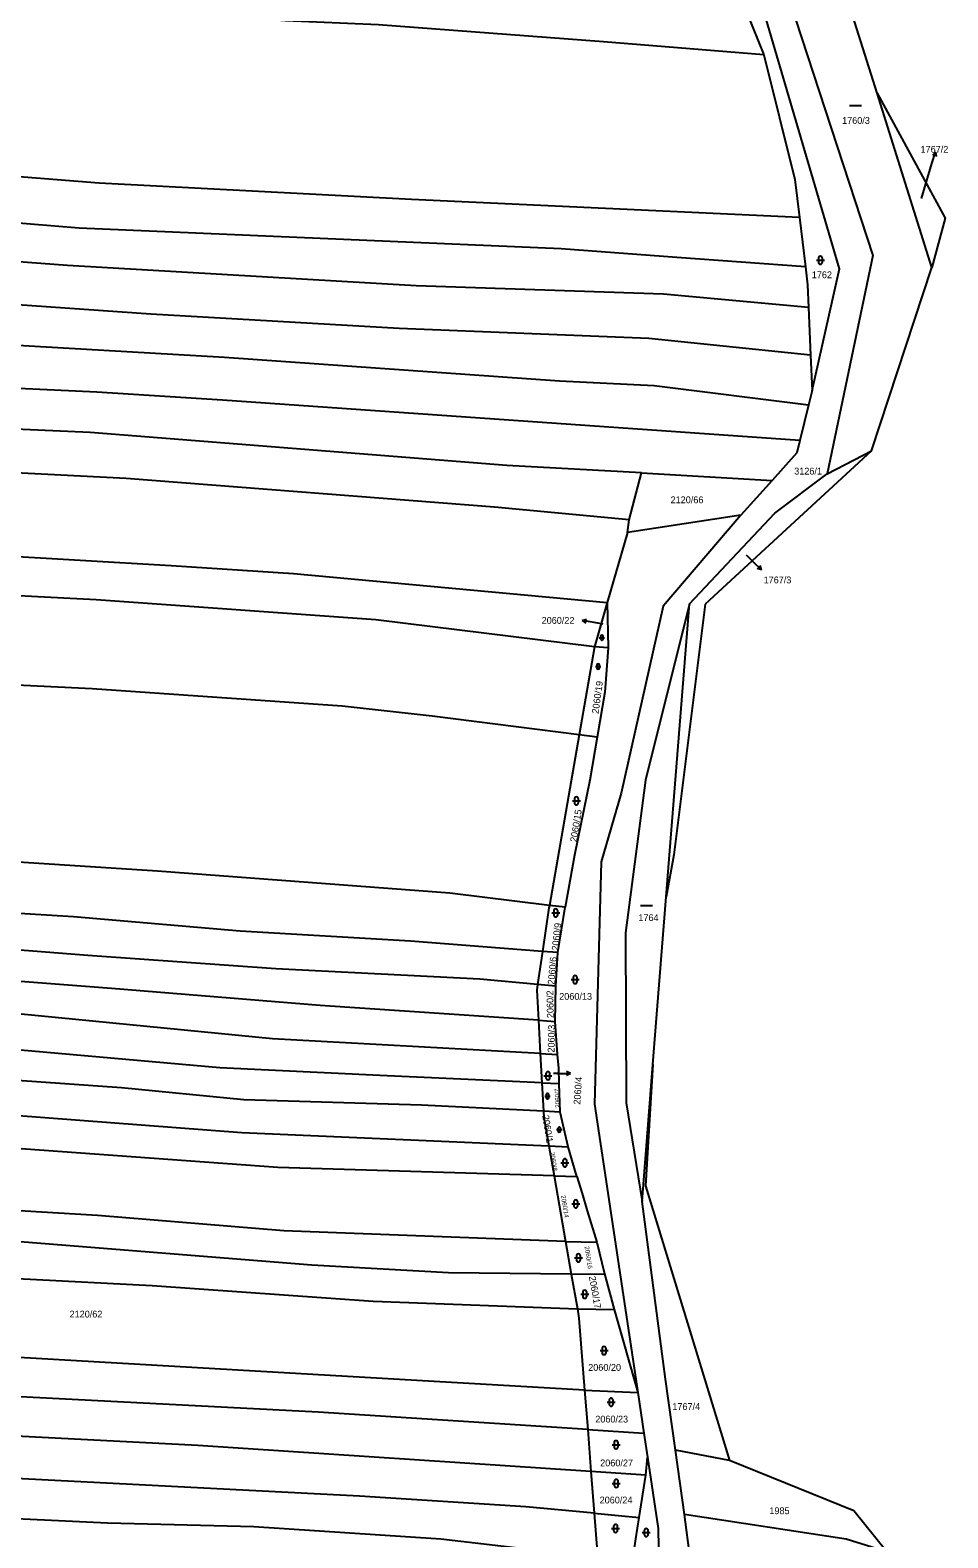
# Model space of a CAD drawing. Extents: x -755528 to -748832, y -1118122 to -1111095.
# Drawn here: x -753247.8 to -753018, y -1116748.3 to -1116370.9 of the extents above; entities that cross this region are included whole.
import ezdxf

# ---------------------------------------------------------------- set-up
doc = ezdxf.new("R2010")
doc.units = 0
for name, color, linetype in [('DZ_DO_PUPFL', 7, 'Continuous'), ('DZ_NAD_ZPF', 7, 'Continuous'), ('legenda barvy', 7, 'Continuous'), ('TZ_UMVŽST', 7, 'Continuous')]:
    doc.layers.add(name, color=color, linetype=linetype)

msp = doc.modelspace()

# ---------------------------------------------------------------- linework, layer by layer
at = {"layer": 'DZ_NAD_ZPF'}
for p, q in [((-753035.72, -1116386.71), (-753043.48, -1116361.95)), ((-753068.32, -1116366.58), (-753064.04, -1116377.12)), ((-753022.04, -1116430.33), (-753035.72, -1116386.71)), ((-753055.15, -1116417.85), (-753053.67, -1116430.18)), ((-753037.1, -1116476.19), (-753022.04, -1116430.33)), ((-753052.89, -1116440.36), (-753052.37, -1116452.3)), ((-753052.37, -1116452.3), (-753051.98, -1116461.16)), ((-753051.98, -1116461.16), (-753052.87, -1116464.8)), ((-753052.87, -1116464.8), (-753055.04, -1116473.63)), ((-753037.1, -1116476.19), (-753078.79, -1116514.61)), ((-753048.23, -1116481.98), (-753037.1, -1116476.19)), ((-753097.82, -1116493.49), (-753094.72, -1116481.73)), ((-753094.72, -1116481.73), (-753062.02, -1116483.62)), ((-753062.02, -1116483.62), (-753069.85, -1116492.32)), ((-753069.85, -1116492.32), (-753098.18, -1116496.71)), ((-753098.18, -1116496.71), (-753097.82, -1116493.49)), ((-753098.18, -1116496.71), (-753103.26, -1116514.2)), ((-753103.26, -1116514.2), (-753106.48, -1116525.3)), ((-753103.26, -1116514.2), (-753103.08, -1116525.57)), ((-753088.48, -1116587.88), (-753082.66, -1116514.55)), ((-753078.79, -1116514.61), (-753086.62, -1116577.36)), ((-753106.48, -1116525.3), (-753110.32, -1116547.29)), ((-753103.08, -1116525.57), (-753106.48, -1116525.3)), ((-753110.32, -1116547.29), (-753117.77, -1116590.01)), ((-753105.78, -1116547.92), (-753110.32, -1116547.29)), ((-753086.62, -1116577.36), (-753088.48, -1116587.88)), ((-753091.82, -1116629.84), (-753088.48, -1116587.88)), ((-753113.79, -1116590.48), (-753117.77, -1116590.01)), ((-753115.61, -1116601.82), (-753113.79, -1116590.48)), ((-753119.5, -1116601.51), (-753120.73, -1116609.8)), ((-753115.61, -1116601.82), (-753119.5, -1116601.51)), ((-753116.16, -1116610.22), (-753115.61, -1116601.82)), ((-753116.16, -1116610.22), (-753120.73, -1116609.8)), ((-753116.32, -1116619.03), (-753116.16, -1116610.22)), ((-753120.51, -1116618.75), (-753116.32, -1116619.03)), ((-753120.51, -1116618.75), (-753120.03, -1116627.07)), ((-753115.75, -1116627.3), (-753116.32, -1116619.03)), ((-753120.03, -1116627.07), (-753115.75, -1116627.3)), ((-753120.03, -1116627.07), (-753119.61, -1116634.4)), ((-753094.54, -1116664.14), (-753091.82, -1116629.84)), ((-753119.61, -1116634.4), (-753119.2, -1116641.49)), ((-753119.61, -1116634.4), (-753115.3, -1116634.59)), ((-753115.03, -1116641.73), (-753115.3, -1116634.59)), ((-753115.03, -1116641.73), (-753119.2, -1116641.49)), ((-753113.04, -1116650.4), (-753115.03, -1116641.73)), ((-753117.87, -1116650.19), (-753116.57, -1116657.66)), ((-753117.87, -1116650.19), (-753113.04, -1116650.4)), ((-753110.88, -1116657.83), (-753113.04, -1116650.4)), ((-753116.57, -1116657.66), (-753110.88, -1116657.83)), ((-753116.57, -1116657.66), (-753113.7, -1116674.1)), ((-753113.7, -1116674.1), (-753105.9, -1116674.32)), ((-753113.7, -1116674.1), (-753112.28, -1116682.26)), ((-753105.9, -1116674.32), (-753103.94, -1116682.22)), ((-753112.28, -1116682.26), (-753103.94, -1116682.22)), ((-753112.28, -1116682.26), (-753110.76, -1116690.99)), ((-753103.94, -1116682.22), (-753101.55, -1116691.1)), ((-753110.76, -1116690.99), (-753101.55, -1116691.1)), ((-753101.55, -1116691.1), (-753095.65, -1116711.88)), ((-753108.94, -1116711.3), (-753095.65, -1116711.88)), ((-753108.94, -1116711.3), (-753108.17, -1116721.19)), ((-753095.65, -1116711.88), (-753094.12, -1116722.1)), ((-753108.17, -1116721.19), (-753094.12, -1116722.1)), ((-753108.17, -1116721.19), (-753107.35, -1116731.69)), ((-753094.12, -1116722.1), (-753093.23, -1116728.07)), ((-753093.58, -1116732.6), (-753093.23, -1116728.07)), ((-753083.97, -1116742.45), (-753086.2, -1116726.32)), ((-753072.62, -1116728.96), (-753086.2, -1116726.32)), ((-753093.58, -1116732.6), (-753107.35, -1116731.69)), ((-753107.35, -1116731.69), (-753106.54, -1116742.11)), ((-753095.25, -1116743.18), (-753093.58, -1116732.6)), ((-753106.54, -1116742.11), (-753095.25, -1116743.18)), ((-753082.48, -1116753.28), (-753083.97, -1116742.45))]:
    msp.add_line(p, q, dxfattribs=at)
for points in [[(-753080.93, -1116306.6), (-753057.65, -1116363.64), (-753036.75, -1116427.3), (-753048.23, -1116481.98)], [(-753051.98, -1116461.16), (-753045.09, -1116430.7), (-753063.87, -1116366.8), (-753089.17, -1116309.16)], [(-753064.04, -1116377.12), (-753104.25, -1116373.86), (-753160.52, -1116369.63), (-753183.87, -1116368.63), (-753300.7, -1116360.15), (-753407.6, -1116353.37), (-753482.36, -1116346.9), (-753577.16, -1116338.42), (-753615.37, -1116334.2), (-753662.17, -1116330.3)], [(-753055.15, -1116417.85), (-753152.31, -1116413.29), (-753230.45, -1116409.21), (-753283.15, -1116405.05), (-753353.24, -1116400.32), (-753415.19, -1116395.32), (-753486.23, -1116390.03), (-753599.85, -1116379.59), (-753670.46, -1116375.3)], [(-753064.04, -1116377.12), (-753056.29, -1116408.34), (-753055.15, -1116417.85)], [(-753053.67, -1116430.18), (-753085.86, -1116427.83), (-753114.81, -1116425.67), (-753235.46, -1116420.46), (-753284.32, -1116416.49), (-753372.74, -1116409.15), (-753409.95, -1116406.88), (-753498.22, -1116401.1), (-753576.32, -1116394.9), (-753643.94, -1116389.17), (-753670.38, -1116387.43)], [(-753035.72, -1116386.71), (-753018.67, -1116417.96), (-753022.04, -1116430.33)], [(-753052.89, -1116440.36), (-753089.2, -1116436.99), (-753151.1, -1116434.97), (-753238.4, -1116429.86), (-753343.18, -1116421.97), (-753441.89, -1116414.39), (-753537.49, -1116408.03), (-753670.32, -1116397.5)], [(-753052.37, -1116452.3), (-753092.82, -1116448.08), (-753155.39, -1116445.6), (-753217.57, -1116442.02), (-753293.95, -1116436.66), (-753394.99, -1116429.88), (-753425.51, -1116426.7), (-753513.73, -1116419.12), (-753575.06, -1116415.73), (-753646.53, -1116409.65), (-753670.26, -1116408.28)], [(-753052.87, -1116464.8), (-753091.55, -1116460), (-753115.19, -1116458.82), (-753199.07, -1116452.86), (-753294.13, -1116447.38), (-753346.4, -1116444.01), (-753446.46, -1116435.5), (-753517.38, -1116429.36), (-753571.65, -1116426.23), (-753670.2, -1116418.61)], [(-753055.04, -1116473.63), (-753199.61, -1116463.54), (-753231.11, -1116461.58), (-753291.76, -1116458.74), (-753351.06, -1116454.14), (-753446.92, -1116446.07), (-753544.62, -1116438.64), (-753670.14, -1116429.12)], [(-753053.67, -1116430.18), (-753053.13, -1116434.72), (-753052.89, -1116440.36)], [(-753094.72, -1116481.73), (-753128.44, -1116479.94), (-753232.75, -1116471.64), (-753296.62, -1116468.8), (-753350.3, -1116464.81), (-753423.98, -1116458.3), (-753499.67, -1116452.31), (-753630.09, -1116442.54), (-753669.86, -1116439.26)], [(-753097.82, -1116493.49), (-753131.52, -1116490.29), (-753223.69, -1116483.13), (-753328.35, -1116477.8), (-753409.55, -1116472.01), (-753516.73, -1116463.2)], [(-753055.04, -1116473.63), (-753055.79, -1116476.7), (-753062.02, -1116483.62)], [(-753106.48, -1116525.3), (-753161.19, -1116518.53), (-753231.25, -1116513.52), (-753287.98, -1116510.58), (-753339.87, -1116507.71), (-753451.87, -1116500.04), (-753528.85, -1116494.44), (-753580.02, -1116490.13), (-753668, -1116483.8)], [(-753082.66, -1116514.55), (-753061.33, -1116491.86), (-753048.23, -1116481.98)], [(-753516.65, -1116484.51), (-753408.18, -1116492.28), (-753303.67, -1116499.59), (-753212.42, -1116504.93), (-753181.8, -1116506.9), (-753103.26, -1116514.2)], [(-753069.85, -1116492.32), (-753089.31, -1116515.12), (-753099.78, -1116561.94), (-753104.82, -1116579.08), (-753106.45, -1116639.73), (-753095.65, -1116711.88)], [(-753110.32, -1116547.29), (-753147.07, -1116542.64), (-753169.63, -1116540.12), (-753232.26, -1116535.78), (-753292.49, -1116532.85), (-753379.65, -1116525.65), (-753447.94, -1116522.54), (-753498.54, -1116518.16), (-753546.82, -1116513.62), (-753672.92, -1116505)], [(-753082.66, -1116514.55), (-753093.68, -1116558.63), (-753098.7, -1116596.86), (-753098.57, -1116639.41), (-753094.54, -1116664.14)], [(-753103.08, -1116525.57), (-753103.84, -1116536.62), (-753105.78, -1116547.92)], [(-753105.78, -1116547.92), (-753107.63, -1116558.62), (-753111.5, -1116577.43), (-753113.79, -1116590.48)], [(-753117.77, -1116590.01), (-753142.67, -1116586.97), (-753215.84, -1116581.41), (-753338.69, -1116573.51), (-753453.85, -1116566.25), (-753560.24, -1116557.34), (-753628.34, -1116552.85), (-753684.94, -1116548.9)], [(-753119.5, -1116601.51), (-753152.5, -1116598.92), (-753195.18, -1116596.48), (-753236.95, -1116592.88), (-753280.41, -1116590.2), (-753356.07, -1116586.47), (-753458.55, -1116577.59), (-753551.39, -1116570), (-753603.3, -1116567.29), (-753639.97, -1116564.72), (-753686.88, -1116561.68)], [(-753120.73, -1116609.8), (-753135.15, -1116608.49), (-753186.22, -1116605.85), (-753233.31, -1116602.56), (-753283.22, -1116598.63), (-753342.44, -1116595.55), (-753426.53, -1116589.69), (-753512.16, -1116581.9), (-753589.34, -1116577.17), (-753645.57, -1116573), (-753687.95, -1116569.77)], [(-753120.51, -1116618.75), (-753175.16, -1116615.05), (-753227.4, -1116610.81), (-753283.87, -1116606.45), (-753334.32, -1116604.33), (-753371.87, -1116602.55), (-753439.51, -1116597.13), (-753519.95, -1116590.26), (-753583.2, -1116585.55), (-753688.11, -1116577.63)], [(-753120.03, -1116627.07), (-753187.11, -1116623.41), (-753250.02, -1116617.19), (-753303.43, -1116613.35), (-753360.24, -1116611.05), (-753425.93, -1116606.46), (-753537.39, -1116597.42), (-753589.17, -1116592.82), (-753629.29, -1116589.75), (-753689.1, -1116586.33)], [(-753117.77, -1116590.01), (-753117.88, -1116590.65), (-753119.5, -1116601.51)], [(-753119.61, -1116634.4), (-753160.2, -1116632.57), (-753200.27, -1116630.64), (-753264.38, -1116624.95), (-753343.29, -1116620.22), (-753416.78, -1116616.19), (-753496.78, -1116610.31), (-753555.04, -1116605.14), (-753612.79, -1116599.7), (-753690.93, -1116594.68)], [(-753119.2, -1116641.49), (-753149.74, -1116639.98), (-753194.27, -1116638.67), (-753224.91, -1116635.7), (-753265.19, -1116632.8), (-753381.97, -1116625.61), (-753432.26, -1116621.91), (-753505.62, -1116617.63), (-753520.93, -1116615.25), (-753583.34, -1116609.73), (-753660.46, -1116604.37), (-753691.22, -1116602.59)], [(-753691.52, -1116610.78), (-753600.79, -1116616.91), (-753502.59, -1116625.81), (-753417.49, -1116632.43), (-753347.21, -1116636.8), (-753277.07, -1116640.61), (-753194.79, -1116646.87), (-753117.87, -1116650.19)], [(-753120.73, -1116609.8), (-753120.94, -1116611.18), (-753120.51, -1116618.75)], [(-753116.57, -1116657.66), (-753185.72, -1116655.57), (-753262.72, -1116650), (-753343.14, -1116644.53), (-753421.14, -1116639.55), (-753499.3, -1116633.88), (-753572.2, -1116628.31), (-753650.2, -1116621.85), (-753692.11, -1116619)], [(-753115.3, -1116634.59), (-753115.39, -1116630.7), (-753115.75, -1116627.3)], [(-753091.82, -1116629.84), (-753093.69, -1116660.21), (-753072.62, -1116728.96)], [(-753113.7, -1116674.1), (-753184.28, -1116671.43), (-753230.92, -1116667.63), (-753302.09, -1116663.36), (-753346.03, -1116660.91), (-753369.09, -1116659.88), (-753452.17, -1116652.28), (-753531.92, -1116647.85), (-753588.93, -1116643.89), (-753693.33, -1116634.36)], [(-753112.28, -1116682.26), (-753143.04, -1116681.96), (-753177.27, -1116680.01), (-753249.3, -1116674.3), (-753338.53, -1116670.13), (-753365.38, -1116668.86), (-753404.76, -1116665.41), (-753438.55, -1116662.23), (-753528.82, -1116656.42), (-753589.87, -1116652.44), (-753648.02, -1116647.27), (-753693.98, -1116642.62)], [(-753119.2, -1116641.49), (-753119.11, -1116643.08), (-753117.87, -1116650.19)], [(-753110.88, -1116657.83), (-753109.59, -1116662.14), (-753108.27, -1116666.43), (-753105.9, -1116674.32)], [(-753086.2, -1116726.32), (-753088.65, -1116708.56), (-753094.54, -1116664.14)], [(-753409.87, -1116673.16), (-753374.3, -1116676.81), (-753341.36, -1116678.85), (-753286.53, -1116681.56), (-753217.25, -1116685.12), (-753161.87, -1116689.03), (-753110.76, -1116690.99)], [(-753108.17, -1116721.19), (-753175.69, -1116716.83), (-753266.56, -1116712.19), (-753376.27, -1116705.64), (-753420.79, -1116703.46), (-753487.86, -1116699.64), (-753570.08, -1116693.1), (-753642.51, -1116686.62), (-753699.29, -1116681.76)], [(-753107.35, -1116731.69), (-753205.79, -1116725.18), (-753301.79, -1116720.22), (-753356.45, -1116717.9), (-753461.67, -1116711.76), (-753564.03, -1116704.34), (-753655.25, -1116696.46), (-753702.04, -1116690.26)], [(-753110.76, -1116690.99), (-753110.35, -1116693.33), (-753108.94, -1116711.3)], [(-753108.94, -1116711.3), (-753177.01, -1116707.37), (-753364.68, -1116696.59), (-753411.06, -1116693.38)], [(-753106.54, -1116742.11), (-753123.64, -1116740.5), (-753165.33, -1116737.82), (-753309.88, -1116730.42), (-753409.98, -1116725.28), (-753491.42, -1116720.46), (-753545.86, -1116715.21), (-753574.03, -1116711.78), (-753642.9, -1116705.03), (-753704.07, -1116695.71)], [(-753691.95, -1116706.77), (-753643.72, -1116716.2), (-753541.02, -1116725.82), (-753441.66, -1116735.38), (-753390.15, -1116736.89), (-753228.4, -1116744.56), (-753191.78, -1116745.46), (-753144.93, -1116748.5), (-753118.45, -1116751.61), (-753105.5, -1116753.63)], [(-753093.23, -1116728.07), (-753090.55, -1116745.92), (-753090.36, -1116755.4), (-753100.53, -1116786.86)], [(-753033.24, -1116751.75), (-753041.57, -1116741.52), (-753072.62, -1116728.96)], [(-753106.54, -1116742.11), (-753105.79, -1116751.69), (-753105.5, -1116753.63)], [(-753097.06, -1116754.82), (-753096.15, -1116748.55), (-753095.25, -1116743.18)], [(-753033.24, -1116751.75), (-753043.44, -1116748.63), (-753083.97, -1116742.45)]]:
    msp.add_lwpolyline(points, dxfattribs=at)
at = {"layer": 'legenda barvy'}
for p, q in [((-753024.59, -1116413.11), (-753021.96, -1116404.35)), ((-753021.96, -1116404.35), (-753021.083, -1116401.48)), ((-753021.083, -1116401.48), (-753021.854, -1116402.291)), ((-753021.083, -1116401.48), (-753020.897, -1116402.584)), ((-753068.48, -1116502.3), (-753066.81, -1116503.92)), ((-753066.81, -1116503.92), (-753064.651, -1116506.005)), ((-753064.651, -1116506.005), (-753065.72, -1116505.669)), ((-753064.651, -1116506.005), (-753065.024, -1116504.949)), ((-753109.515, -1116518.669), (-753108.442, -1116518.35)), ((-753106.56, -1116519.19), (-753109.515, -1116518.669)), ((-753109.515, -1116518.669), (-753108.616, -1116519.336)), ((-753104.29, -1116519.59), (-753106.56, -1116519.19)), ((-753115.5, -1116632.1), (-753116.71, -1116632.1)), ((-753115.5, -1116632.1), (-753112.499, -1116632.1)), ((-753112.499, -1116632.1), (-753113.5, -1116631.599)), ((-753112.499, -1116632.1), (-753113.5, -1116632.601))]:
    msp.add_line(p, q, dxfattribs=at)
at = {"layer": 'TZ_UMVŽST'}
for p, q in [((-753042.628, -1116389.83), (-753039.628, -1116389.83)), ((-753050.911, -1116428.511), (-753048.909, -1116428.511)), ((-753050.411, -1116428.011), (-753050.411, -1116429.012)), ((-753049.409, -1116429.012), (-753049.409, -1116428.011)), ((-753105.261, -1116523.001), (-753103.919, -1116523.001)), ((-753104.925, -1116522.665), (-753104.925, -1116523.336)), ((-753104.255, -1116523.336), (-753104.255, -1116522.665)), ((-753106.211, -1116530.211), (-753104.869, -1116530.211)), ((-753105.875, -1116529.875), (-753105.875, -1116530.546)), ((-753105.205, -1116530.546), (-753105.205, -1116529.875)), ((-753111.511, -1116563.331), (-753111.511, -1116564.332)), ((-753110.509, -1116564.332), (-753110.509, -1116563.331)), ((-753112.011, -1116563.831), (-753110.009, -1116563.831)), ((-753117.171, -1116591.881), (-753115.169, -1116591.881)), ((-753116.671, -1116591.381), (-753116.671, -1116592.382)), ((-753115.669, -1116592.382), (-753115.669, -1116591.381)), ((-753094.948, -1116590.06), (-753091.948, -1116590.06)), ((-753112.311, -1116608.571), (-753110.309, -1116608.571)), ((-753111.811, -1116608.071), (-753111.811, -1116609.072)), ((-753110.809, -1116609.072), (-753110.809, -1116608.071)), ((-753119.121, -1116632.641), (-753117.119, -1116632.641)), ((-753118.621, -1116632.141), (-753118.621, -1116633.142)), ((-753117.619, -1116633.142), (-753117.619, -1116632.141)), ((-753118.881, -1116637.761), (-753117.539, -1116637.761)), ((-753118.545, -1116637.425), (-753118.545, -1116638.096)), ((-753117.875, -1116638.096), (-753117.875, -1116637.425)), ((-753115.941, -1116646.121), (-753114.599, -1116646.121)), ((-753115.605, -1116645.785), (-753115.605, -1116646.456)), ((-753114.935, -1116646.456), (-753114.935, -1116645.785)), ((-753114.371, -1116653.931), (-753114.371, -1116654.932)), ((-753113.369, -1116654.932), (-753113.369, -1116653.931)), ((-753114.871, -1116654.431), (-753112.869, -1116654.431)), ((-753112.141, -1116664.701), (-753110.139, -1116664.701)), ((-753111.641, -1116664.201), (-753111.641, -1116665.202)), ((-753110.639, -1116665.202), (-753110.639, -1116664.201)), ((-753111.501, -1116678.211), (-753109.499, -1116678.211)), ((-753111.001, -1116677.711), (-753111.001, -1116678.712)), ((-753109.999, -1116678.712), (-753109.999, -1116677.711)), ((-753109.921, -1116687.341), (-753107.919, -1116687.341)), ((-753109.421, -1116686.841), (-753109.421, -1116687.842)), ((-753108.419, -1116687.842), (-753108.419, -1116686.841)), ((-753105.081, -1116701.441), (-753103.079, -1116701.441)), ((-753104.581, -1116700.941), (-753104.581, -1116701.942)), ((-753103.579, -1116701.942), (-753103.579, -1116700.941)), ((-753103.301, -1116714.331), (-753101.299, -1116714.331)), ((-753102.801, -1116713.831), (-753102.801, -1116714.832)), ((-753101.799, -1116714.832), (-753101.799, -1116713.831)), ((-753102.071, -1116724.981), (-753100.069, -1116724.981)), ((-753101.571, -1116724.481), (-753101.571, -1116725.482)), ((-753100.569, -1116725.482), (-753100.569, -1116724.481)), ((-753102.001, -1116734.671), (-753099.999, -1116734.671)), ((-753101.501, -1116734.171), (-753101.501, -1116735.172)), ((-753100.499, -1116735.172), (-753100.499, -1116734.171)), ((-753102.191, -1116745.931), (-753100.189, -1116745.931)), ((-753101.691, -1116745.431), (-753101.691, -1116746.432)), ((-753100.689, -1116746.432), (-753100.689, -1116745.431)), ((-753094.521, -1116746.961), (-753092.519, -1116746.961)), ((-753094.021, -1116746.461), (-753094.021, -1116747.462)), ((-753093.019, -1116747.462), (-753093.019, -1116746.461))]:
    msp.add_line(p, q, dxfattribs=at)
for centre, radius, start, end in [((-753049.91, -1116428.0109), 0.5, 0, 180), ((-753049.91, -1116429.0109), 0.5, 180, 359.987886), ((-753104.59, -1116522.6656), 0.335, 0, 180), ((-753104.59, -1116523.3356), 0.335, 180, 359.987886), ((-753105.54, -1116529.8756), 0.335, 0, 180), ((-753105.54, -1116530.5456), 0.335, 180, 359.987886), ((-753111.01, -1116563.3309), 0.5, 0, 180), ((-753111.01, -1116564.3309), 0.5, 180, 359.987886), ((-753116.17, -1116591.3809), 0.5, 0, 180), ((-753116.17, -1116592.3809), 0.5, 180, 359.987886), ((-753111.31, -1116608.0709), 0.5, 0, 180), ((-753111.31, -1116609.0709), 0.5, 180, 359.987886), ((-753118.12, -1116632.1409), 0.5, 0, 180), ((-753118.12, -1116633.1409), 0.5, 180, 359.987886), ((-753118.21, -1116637.4256), 0.335, 0, 180), ((-753118.21, -1116638.0956), 0.335, 180, 359.987886), ((-753115.27, -1116645.7856), 0.335, 0, 180), ((-753115.27, -1116646.4556), 0.335, 180, 359.987886), ((-753113.87, -1116653.9309), 0.5, 0, 180), ((-753113.87, -1116654.9309), 0.5, 180, 359.987886), ((-753111.14, -1116664.2009), 0.5, 0, 180), ((-753111.14, -1116665.2009), 0.5, 180, 359.987886), ((-753110.5, -1116677.7109), 0.5, 0, 180), ((-753110.5, -1116678.7109), 0.5, 180, 359.987886), ((-753108.92, -1116686.8409), 0.5, 0, 180), ((-753108.92, -1116687.8409), 0.5, 180, 359.987886), ((-753104.08, -1116700.9409), 0.5, 0, 180), ((-753104.08, -1116701.9409), 0.5, 180, 359.987886), ((-753102.3, -1116713.8309), 0.5, 0, 180), ((-753102.3, -1116714.8309), 0.5, 180, 359.987886), ((-753101.07, -1116724.4809), 0.5, 0, 180), ((-753101.07, -1116725.4809), 0.5, 180, 359.987886), ((-753101, -1116734.1709), 0.5, 0, 180), ((-753101, -1116735.1709), 0.5, 180, 359.987886), ((-753101.19, -1116745.4309), 0.5, 0, 180), ((-753101.19, -1116746.4309), 0.5, 180, 359.987886), ((-753093.52, -1116746.4609), 0.5, 0, 180), ((-753093.52, -1116747.4609), 0.5, 180, 359.987886)]:
    msp.add_arc(centre, radius, start, end, dxfattribs=at)

# ---------------------------------------------------------------- texts
at = {"layer": 'DZ_DO_PUPFL'}
for s, p in [('1760/3', (-753044.47, -1116394.4)), ('1767/2', (-753024.827, -1116401.61)), ('1762', (-753052.06, -1116433.02)), ('3126/1', (-753056.46, -1116482.16)), ('2120/66', (-753087.41, -1116489.34)), ('1767/3', (-753064.13, -1116509.388)), ('2060/22', (-753119.703, -1116519.52)), ('1764', (-753095.48, -1116593.92)), ('2060/13', (-753115.3, -1116613.62)), ('2120/62', (-753237.9, -1116693.14)), ('2060/20', (-753108.04, -1116706.49)), ('1767/4', (-753086.967, -1116716.28)), ('2060/23', (-753106.27, -1116719.42)), ('2060/27', (-753105.04, -1116730.39)), ('2060/24', (-753105.18, -1116739.68)), ('1985', (-753062.68, -1116742.36))]:
    msp.add_text(s, height=1.7, dxfattribs=at).set_placement(p)
for s, height, rotation, p in [('2060/19', 1.7, 82, (-753105.468, -1116542.098)), ('2060/15', 1.7, 81, (-753110.92, -1116574.262)), ('2060/9', 1.7, 84, (-753115.504, -1116601.388)), ('2060/6', 1.7, 85, (-753116.503, -1116609.874)), ('2060/2', 1.7, 91, (-753116.67, -1116618.195)), ('2060/3', 1.7, 89, (-753116.48, -1116626.844)), ('2060/4', 1.7, 86, (-753110.028, -1116639.908)), ('2060/7', 1.14, 92, (-753115.107, -1116640.655)), ('2060/1', 1.7, 279, (-753119.549, -1116642.612)), ('2060/8', 1.14, 279, (-753117.617, -1116651.814)), ('2060/14', 1.14, 280, (-753114.906, -1116662.643)), ('2060/16', 1.14, 279, (-753108.955, -1116675.414)), ('2060/17', 1.7, 280, (-753107.877, -1116682.927))]:
    msp.add_text(s, height=height, rotation=rotation, dxfattribs=at).set_placement(p)

doc.saveas('drawing.dxf')
